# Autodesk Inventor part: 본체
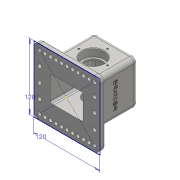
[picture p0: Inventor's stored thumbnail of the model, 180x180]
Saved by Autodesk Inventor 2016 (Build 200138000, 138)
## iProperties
Created: 2018-11
Part Number: 본체
Material: 일반
Document SubType Name: Modeling
Designer: 605-04
Density: 1 g/cm^3
Appearance: 기본값
Author: 605-04
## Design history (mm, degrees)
sketch "스케치1"
  geometry: L1 (-60, 60)-(60, 60); L2 (60, 60)-(60, -60); L3 (60, -60)-(-60, -60); L4 (-60, -60)-(-60, 60); L5 (-60, 60)-(60, -60); L6 (60, 60)-(-60, -60); L7 (-60, 60)-(60, 60); L8 (60, 60)-(60, -60); L9 (60, -60)-(-60, -60); L10 (-60, -60)-(-60, 60); L11 (-60, 60)-(60, -60); L12 (60, 60)-(-60, -60); 1 further point
  constraints: 24 end point, 4 midpoint, 4 parallel, 2 horizontal, 2 perpendicular
  dimensions: "d90" = 120 distance of L2.end L3.end; "d91" = 120 distance of L1.end L2.end
extrude "돌출1" new body sketch "스케치1" distance "d1" = 10; taper "d2" = 0 deg
sketch "스케치2"
  geometry: L1 (40, -40)-(-40, -40); L2 (-40, -40)-(-40, 40); L3 (-40, 40)-(40, 40); L4 (40, 40)-(40, -40); L5 (40, -40)-(-40, 40); L6 (-40, -40)-(40, 40); 1 further point
  constraints: 12 end point, 2 midpoint, 2 parallel, 1 horizontal, 1 perpendicular
  dimensions: "d3" = 80 distance of L2.end L3.end; "d85" = 80 distance of L1.end L2.end
extrude "돌출2" join sketch "스케치2" distance "d4" = 80; taper "d5" = 0 deg
sketch "스케치3"
  geometry: C1 r 7.5 at (0, 0); 1 further point
  constraints: 1 centre point, 1 coincident
  dimensions: "d6" = 15 diameter of C1
extrude "돌출3" join sketch "스케치3" distance "d7" = 5; taper "d8" = 0 deg
sketch "스케치5"
  geometry: L1 (-30, -23)-(30, -23); L2 (30, -23)-(30, 23); L3 (30, 23)-(-30, 23); L4 (-30, 23)-(-30, -23); L5 (-30, -23)-(30, 23); L6 (30, -23)-(-30, 23); 1 further point
  constraints: 12 end point, 2 midpoint, 2 parallel, 1 horizontal, 1 perpendicular
  dimensions: "d9" = 46 distance of L1.end L2.end; "d26" = 60 distance of L2.end L3.end
extrude "돌출4" cut sketch "스케치5" distance "d10" = 80; taper "d11" = 0 deg
sketch "스케치6"
  geometry: L1 (100, -10)-(-20, -10) reference; C1 r 20 at (40, 38); 1 further point
  constraints: 1 centre point
  dimensions: "d12" = 48 distance from line of L1 C1.centre; "d13" = 40 diameter of C1
extrude "돌출5" cut sketch "스케치6" distance "d14" = 14; taper "d15" = 0 deg
sketch "스케치7"
  geometry: C1 r 16.5 at (0, 0); 1 further point
  constraints: 1 centre point
  dimensions: "d16" = 33 diameter of C1
extrude "돌출6" cut sketch "스케치7" distance "d17" = 3; taper "d18" = 0 deg
sketch "스케치8"
  geometry: 2 further points
  constraints: 1 coincident
hole "구멍1" sketch "스케치8" at (0, 0) diameter "d19" = 4.917; stored, may be unused: countersink angle "d23" = 90 deg, drill point angle "d25" = 118 deg; dims "d20" = 12, "d21" = 4, "d22" = 2, "d24" = 17.1
sketch "스케치9" dims "d27" = 52
  geometry: C1 r 16.5 at (40, 38) reference; 3 further points
  constraints: 1 coincident, 1 vertical alignment, 2 other
hole "구멍2" sketch "스케치9" at (40, 64) diameter "d28" = 3.242; stored, may be unused: countersink angle "d32" = 90 deg, drill point angle "d34" = 118 deg; dims "d29" = 8, "d30" = 4, "d31" = 2, "d33" = 10
chamfer "모따기1" distance "d38" = 1; stored, may be unused: second distance "d39" = 2, angle "d40" = 45 deg
fillet "모깎기1" dims "d41" = 0.6
fillet "모깎기3" dims "d43" = 8
fillet "모깎기5" dims "d61" = 10
fillet "모깎기6" dims "d62" = 3
sketch "스케치11"
  geometry: A1 r 10 centre (-50, 50) between (-50, 60) and (-60, 50) reference; A2 r 10 centre (50, 50) between (60, 50) and (50, 60) reference; A3 r 7 centre (50, -50) between (50, -57) and (57, -50) reference; A4 r 7 centre (-50, -50) between (-57, -50) and (-50, -57) reference; 17 further points
  constraints: 4 coincident
  dimensions: "d63" = 10 distance of point (-30, 50) point (-40, 50); "d64" = 10 distance of point (-20, 50) point (-30, 50); "d65" = 10 distance of point (-20, 50) point (-10, 50); "d66" = 10 distance of point (0, 50) point (-10, 50); "d67" = 10 distance of point (10, 50) point (0, 50); "d68" = 10 distance of point (20, 50) point (10, 50); "d69" = 10 distance of point (30, 50) point (20, 50); "d70" = 10 distance of point (40, 50) point (30, 50); "d71" = 25 distance of point (-50, 50) point (-50, 25); "d72" = 25 distance of point (-50, -1.665) point (-50, -26.665)
hole "구멍3" sketch "스케치11" at (-50, -50), (-50, -26.665), (-50, -1.665), (-50, 25), (-50, 50), (-40, 50), (-30, 50), (-20, 50), (-10, 50), (0, 50), (10, 50), (20, 50)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 diameter "d73" = 6.6; stored, may be unused: countersink angle "d77" = 90 deg, drill point angle "d79" = 0 deg; dims "d74" = 8, "d75" = 4, "d76" = 2, "d78" = 10
fillet "모깎기7" dims "d80" = 3
sketch "스케치12"
  geometry: L1 (82, -82)-(-18, -82) reference; 3 further points
  constraints: 1 midpoint, 1 vertical alignment, 1 other
  dimensions: "d82" = 48 distance from line of L1 point (32, -34)
feature "엠보싱1" sketch "스케치12" dims "d83" = 0.5, "d84" = 0, "d90" = 120, "d91" = 120
node "솔리드1"
mirror "대칭1"
mirror "대칭2"
pattern_circular "원형 패턴1" dims angle "d36" = 360 deg
mirror "대칭3"
mirror "대칭4"
mirror "대칭5"
